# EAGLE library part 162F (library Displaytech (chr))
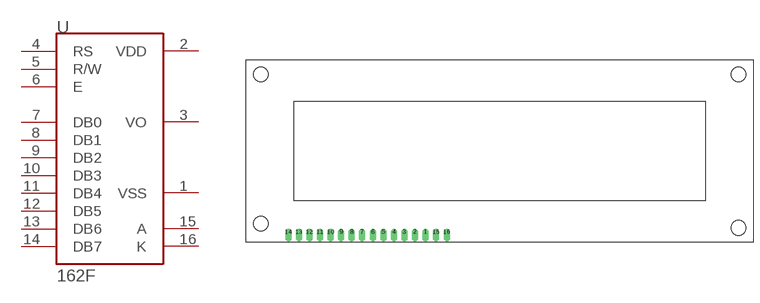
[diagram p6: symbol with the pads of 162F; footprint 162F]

Designator prefix -

## 162F  [162F]
1  VSS  pwr
2  VDD  pwr
3  VO  in
4  RS
5  R/W
6  E
7  DB0
8  DB1
9  DB2
10  DB3
11  DB4
12  DB5
13  DB6
14  DB7
15  A  pwr
16  K  pwr

## Footprint 162F (pad centres in mm)
drill 1.016 offset: 1 33.02,0; 2 30.48,0; 3 27.94,0; 4 25.4,0; 5 22.86,0; 6 20.32,0; 7 17.78,0; 8 15.24,0; 9 12.7,0; 10 10.16,0; 11 7.62,0; 12 5.08,0; 13 2.54,0; 14 0,0; 15 35.56,0; 16 38.1,0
